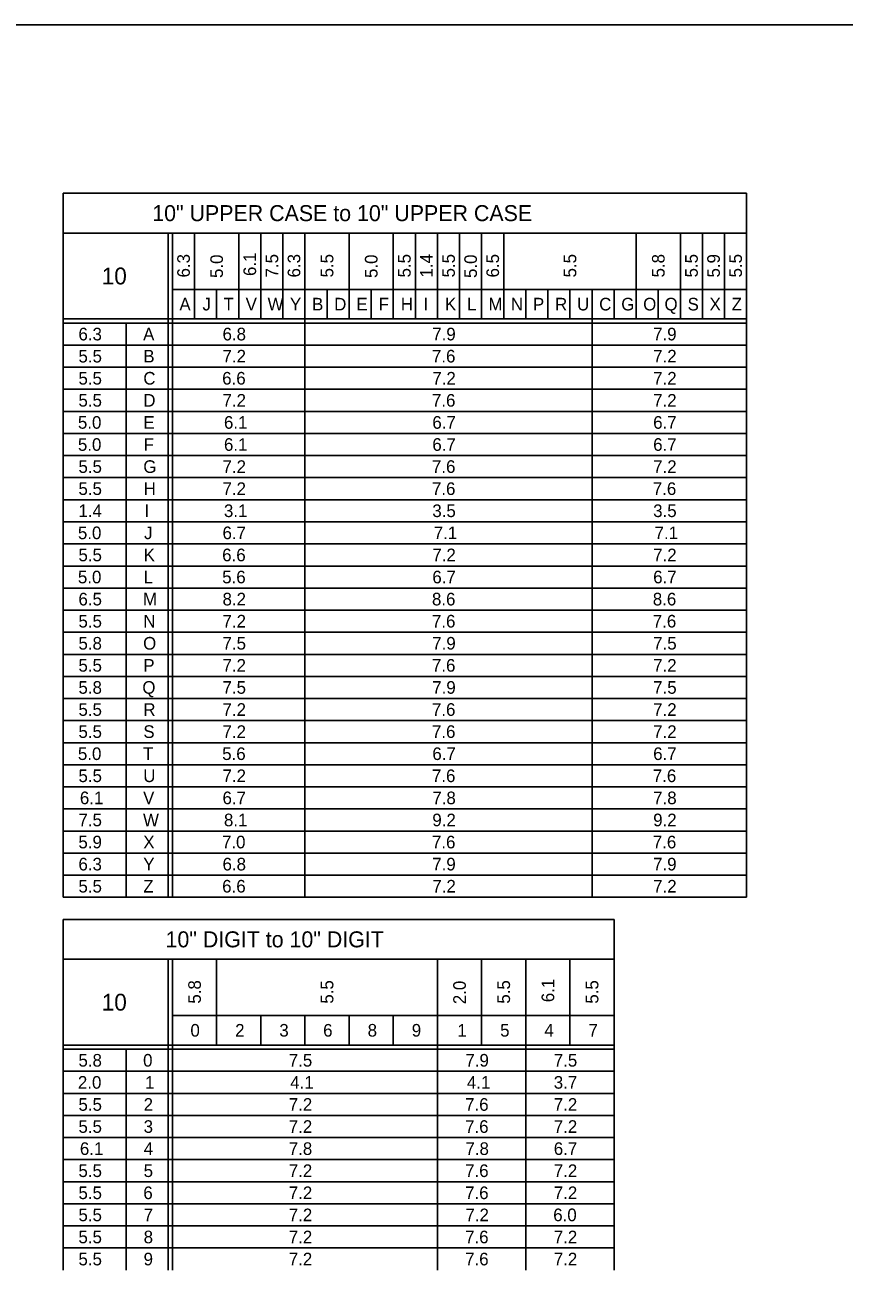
# Model space of a CAD drawing. Extents: x 637580 to 641849, y 297270 to 299646.
# Drawn here: x 640540.8 to 640735.6, y 297552.6 to 297848.6 of the extents above; entities that cross this region are included whole.
import ezdxf

# ---------------------------------------------------------------- set-up
doc = ezdxf.new("R2010")
doc.units = 0
doc.layers.add('1', color=7, linetype='Continuous')
doc.layers.add('2', color=7, linetype='Continuous')

msp = doc.modelspace()

# ---------------------------------------------------------------- linework, layer by layer
at = {"layer": '1'}
msp.add_line((640143.31, 297848.63), (640929.31, 297848.63), dxfattribs=at)
at = {"layer": '2'}
for p, q in [((640712.41, 297808.63), (640549.91, 297808.63)), ((640549.91, 297808.63), (640549.91, 297641.25)), ((640712.41, 297808.63), (640712.41, 297641.25)), ((640549.91, 297799.13), (640712.41, 297799.13)), ((640574.91, 297799.13), (640574.91, 297641.25)), ((640575.91, 297799.13), (640575.91, 297641.25)), ((640581.16, 297799.13), (640581.16, 297778.75)), ((640591.66, 297799.13), (640591.66, 297778.75)), ((640596.91, 297799.13), (640596.91, 297778.75)), ((640602.16, 297799.13), (640602.16, 297778.75)), ((640607.41, 297799.13), (640607.41, 297641.25)), ((640617.91, 297799.13), (640617.91, 297778.75)), ((640628.41, 297799.13), (640628.41, 297778.75)), ((640633.66, 297799.13), (640633.66, 297778.75)), ((640638.91, 297799.13), (640638.91, 297778.75)), ((640644.16, 297799.13), (640644.16, 297778.75)), ((640649.41, 297799.13), (640649.41, 297778.75)), ((640654.66, 297799.13), (640654.66, 297778.75)), ((640686.16, 297799.13), (640686.16, 297778.75)), ((640696.66, 297799.13), (640696.66, 297778.75)), ((640701.91, 297799.13), (640701.91, 297778.75)), ((640707.16, 297799.13), (640707.16, 297778.75)), ((640575.91, 297785.75), (640712.41, 297785.75)), ((640586.41, 297785.75), (640586.41, 297778.75)), ((640612.66, 297785.75), (640612.66, 297778.75)), ((640623.16, 297785.75), (640623.16, 297778.75)), ((640659.91, 297785.75), (640659.91, 297778.75)), ((640665.16, 297785.75), (640665.16, 297778.75)), ((640670.41, 297785.75), (640670.41, 297778.75)), ((640670.41, 297785.75), (640670.41, 297778.75)), ((640675.66, 297785.75), (640675.66, 297641.25)), ((640680.91, 297785.75), (640680.91, 297778.75)), ((640691.41, 297785.75), (640691.41, 297778.75)), ((640712.41, 297778.75), (640549.91, 297778.75)), ((640712.41, 297777.75), (640549.91, 297777.75)), ((640564.91, 297777.75), (640564.91, 297641.25)), ((640712.41, 297772.5), (640549.91, 297772.5)), ((640712.41, 297767.25), (640549.91, 297767.25)), ((640712.41, 297762), (640549.91, 297762)), ((640712.41, 297756.75), (640549.91, 297756.75)), ((640712.41, 297751.5), (640549.91, 297751.5)), ((640712.41, 297746.25), (640549.91, 297746.25)), ((640712.41, 297741), (640549.91, 297741)), ((640712.41, 297735.75), (640549.91, 297735.75)), ((640712.41, 297730.5), (640549.91, 297730.5)), ((640712.41, 297725.25), (640549.91, 297725.25)), ((640712.41, 297720), (640549.91, 297720)), ((640712.41, 297714.75), (640549.91, 297714.75)), ((640712.41, 297709.5), (640549.91, 297709.5)), ((640712.41, 297704.25), (640549.91, 297704.25)), ((640712.41, 297699), (640549.91, 297699)), ((640712.41, 297693.75), (640549.91, 297693.75)), ((640712.41, 297688.5), (640549.91, 297688.5)), ((640712.41, 297683.25), (640549.91, 297683.25)), ((640712.41, 297678), (640549.91, 297678)), ((640712.41, 297672.75), (640549.91, 297672.75)), ((640712.41, 297667.5), (640549.91, 297667.5)), ((640712.41, 297662.25), (640549.91, 297662.25)), ((640712.41, 297657), (640549.91, 297657)), ((640712.41, 297651.75), (640549.91, 297651.75)), ((640712.41, 297646.5), (640549.91, 297646.5)), ((640549.91, 297641.25), (640549.91, 297641.25)), ((640549.91, 297641.25), (640712.41, 297641.25)), ((640680.91, 297636), (640549.91, 297636)), ((640549.91, 297636), (640549.91, 297552.63)), ((640680.91, 297552.63), (640680.91, 297636)), ((640549.91, 297626.5), (640680.91, 297626.5)), ((640574.91, 297626.5), (640574.91, 297552.63)), ((640575.91, 297626.5), (640575.91, 297552.63)), ((640586.41, 297626.5), (640586.41, 297606.13)), ((640638.91, 297626.5), (640638.91, 297552.63)), ((640649.41, 297626.5), (640649.41, 297606.13)), ((640659.91, 297626.5), (640659.91, 297552.63)), ((640670.41, 297626.5), (640670.41, 297606.13)), ((640575.91, 297613.13), (640680.91, 297613.13)), ((640596.91, 297613.13), (640596.91, 297606.13)), ((640607.41, 297613.13), (640607.41, 297606.13)), ((640617.91, 297613.13), (640617.91, 297606.13)), ((640628.41, 297613.13), (640628.41, 297606.13)), ((640680.91, 297606.13), (640549.91, 297606.13)), ((640680.91, 297605.13), (640549.91, 297605.13)), ((640564.91, 297605.13), (640564.91, 297552.63)), ((640680.91, 297599.88), (640549.91, 297599.88)), ((640680.91, 297594.63), (640549.91, 297594.63)), ((640680.91, 297589.38), (640549.91, 297589.38)), ((640680.91, 297584.13), (640549.91, 297584.13)), ((640680.91, 297578.88), (640549.91, 297578.88)), ((640680.91, 297573.63), (640549.91, 297573.63)), ((640680.91, 297568.38), (640549.91, 297568.38)), ((640680.91, 297563.13), (640549.91, 297563.13)), ((640680.91, 297557.88), (640549.91, 297557.88))]:
    msp.add_line(p, q, dxfattribs=at)

# ---------------------------------------------------------------- texts
for s, height, p in [('10" UPPER CASE to 10" UPPER CASE', 3.8, (640571.1, 297801.98)), ('10', 4, (640559.1, 297786.94)), ('A', 3, (640577.56, 297780.75)), ('J', 3, (640583.04, 297780.75)), ('T', 3, (640588.04, 297780.75)), ('V', 3, (640593.31, 297780.75)), ('W', 3, (640598.53, 297780.75)), ('Y', 3, (640603.84, 297780.75)), ('B', 3, (640609.1, 297780.75)), ('D', 3, (640614.35, 297780.75)), ('E', 3, (640619.62, 297780.75)), ('F', 3, (640624.92, 297780.75)), ('H', 3, (640630.19, 297780.75)), ('I', 3, (640635.6, 297780.75)), ('K', 3, (640640.69, 297780.75)), ('L', 3, (640645.94, 297780.75)), ('M', 3, (640651.03, 297780.75)), ('N', 3, (640656.35, 297780.75)), ('P', 3, (640661.6, 297780.75)), ('R', 3, (640666.85, 297780.75)), ('U', 3, (640672.09, 297780.75)), ('C', 3, (640677.35, 297780.75)), ('G', 3, (640682.6, 297780.75)), ('O', 3, (640687.81, 297780.75)), ('Q', 3, (640692.88, 297780.75)), ('S', 3, (640698.37, 297780.75)), ('X', 3, (640703.59, 297780.75)), ('Z', 3, (640708.85, 297780.75)), ('6.3', 3, (640553.56, 297773.63)), ('A', 3, (640568.93, 297773.63)), ('6.8', 3, (640587.81, 297773.63)), ('7.9', 3, (640637.67, 297773.63)), ('7.9', 3, (640690.17, 297773.63)), ('5.5', 3, (640553.56, 297768.38)), ('B', 3, (640568.98, 297768.38)), ('7.2', 3, (640587.81, 297768.38)), ('7.6', 3, (640637.6, 297768.38)), ('7.2', 3, (640690.19, 297768.38)), ('5.5', 3, (640553.56, 297763.13)), ('C', 3, (640568.98, 297763.13)), ('6.6', 3, (640587.73, 297763.13)), ('7.2', 3, (640637.69, 297763.13)), ('7.2', 3, (640690.19, 297763.13)), ('5.5', 3, (640553.56, 297757.88)), ('D', 3, (640568.98, 297757.88)), ('7.2', 3, (640587.81, 297757.88)), ('7.6', 3, (640637.6, 297757.88)), ('7.2', 3, (640690.19, 297757.88)), ('5.0', 3, (640553.43, 297752.63)), ('E', 3, (640568.99, 297752.63)), ('6.1', 3, (640588.15, 297752.63)), ('6.7', 3, (640637.69, 297752.63)), ('6.7', 3, (640690.19, 297752.63)), ('5.0', 3, (640553.43, 297747.38)), ('F', 3, (640569.05, 297747.38)), ('6.1', 3, (640588.15, 297747.38)), ('6.7', 3, (640637.69, 297747.38)), ('6.7', 3, (640690.19, 297747.38)), ('5.5', 3, (640553.56, 297742.13)), ('G', 3, (640568.98, 297742.13)), ('7.2', 3, (640587.81, 297742.13)), ('7.6', 3, (640637.6, 297742.13)), ('7.2', 3, (640690.19, 297742.13)), ('5.5', 3, (640553.56, 297736.88)), ('H', 3, (640569.06, 297736.88)), ('7.2', 3, (640587.81, 297736.88)), ('7.6', 3, (640637.6, 297736.88)), ('7.6', 3, (640690.1, 297736.88)), ('1.4', 3, (640553.56, 297731.63)), ('I', 3, (640569.23, 297731.63)), ('3.1', 3, (640588.15, 297731.63)), ('3.5', 3, (640637.69, 297731.63)), ('3.5', 3, (640690.19, 297731.63)), ('5.0', 3, (640553.43, 297726.38)), ('J', 3, (640569.17, 297726.38)), ('6.7', 3, (640587.81, 297726.38)), ('7.1', 3, (640638.03, 297726.38)), ('7.1', 3, (640690.53, 297726.38)), ('5.5', 3, (640553.56, 297721.13)), ('K', 3, (640569.06, 297721.13)), ('6.6', 3, (640587.73, 297721.13)), ('7.2', 3, (640637.69, 297721.13)), ('7.2', 3, (640690.19, 297721.13)), ('5.0', 3, (640553.43, 297715.88)), ('L', 3, (640569.06, 297715.88)), ('5.6', 3, (640587.73, 297715.88)), ('6.7', 3, (640637.69, 297715.88)), ('6.7', 3, (640690.19, 297715.88)), ('6.5', 3, (640553.56, 297710.63)), ('M', 3, (640568.91, 297710.63)), ('8.2', 3, (640587.81, 297710.63)), ('8.6', 3, (640637.6, 297710.63)), ('8.6', 3, (640690.1, 297710.63)), ('5.5', 3, (640553.56, 297705.38)), ('N', 3, (640568.98, 297705.38)), ('7.2', 3, (640587.81, 297705.38)), ('7.6', 3, (640637.6, 297705.38)), ('7.6', 3, (640690.1, 297705.38)), ('5.8', 3, (640553.56, 297700.13)), ('O', 3, (640568.93, 297700.13)), ('7.5', 3, (640587.81, 297700.13)), ('7.9', 3, (640637.67, 297700.13)), ('7.5', 3, (640690.19, 297700.13)), ('5.5', 3, (640553.56, 297694.88)), ('P', 3, (640568.98, 297694.88)), ('7.2', 3, (640587.81, 297694.88)), ('7.6', 3, (640637.6, 297694.88)), ('7.2', 3, (640690.19, 297694.88)), ('5.8', 3, (640553.56, 297689.63)), ('Q', 3, (640568.75, 297689.63)), ('7.5', 3, (640587.81, 297689.63)), ('7.9', 3, (640637.67, 297689.63)), ('7.5', 3, (640690.19, 297689.63)), ('5.5', 3, (640553.56, 297684.38)), ('R', 3, (640568.98, 297684.38)), ('7.2', 3, (640587.81, 297684.38)), ('7.6', 3, (640637.6, 297684.38)), ('7.2', 3, (640690.19, 297684.38)), ('5.5', 3, (640553.56, 297679.13)), ('S', 3, (640568.99, 297679.13)), ('7.2', 3, (640587.81, 297679.13)), ('7.6', 3, (640637.6, 297679.13)), ('7.2', 3, (640690.19, 297679.13)), ('5.0', 3, (640553.43, 297673.88)), ('T', 3, (640568.92, 297673.88)), ('5.6', 3, (640587.73, 297673.88)), ('6.7', 3, (640637.69, 297673.88)), ('6.7', 3, (640690.19, 297673.88)), ('5.5', 3, (640553.56, 297668.63)), ('U', 3, (640568.97, 297668.63)), ('7.2', 3, (640587.81, 297668.63)), ('7.6', 3, (640637.6, 297668.63)), ('7.6', 3, (640690.1, 297668.63)), ('6.1', 3, (640553.9, 297663.38)), ('V', 3, (640568.93, 297663.38)), ('6.7', 3, (640587.81, 297663.38)), ('7.8', 3, (640637.69, 297663.38)), ('7.8', 3, (640690.19, 297663.38)), ('7.5', 3, (640553.56, 297658.13)), ('W', 3, (640568.91, 297658.13)), ('8.1', 3, (640588.15, 297658.13)), ('9.2', 3, (640637.69, 297658.13)), ('9.2', 3, (640690.19, 297658.13)), ('5.9', 3, (640553.55, 297652.88)), ('X', 3, (640568.97, 297652.88)), ('7.0', 3, (640587.68, 297652.88)), ('7.6', 3, (640637.6, 297652.88)), ('7.6', 3, (640690.1, 297652.88)), ('6.3', 3, (640553.56, 297647.63)), ('Y', 3, (640568.97, 297647.63)), ('6.8', 3, (640587.81, 297647.63)), ('7.9', 3, (640637.67, 297647.63)), ('7.9', 3, (640690.17, 297647.63)), ('5.5', 3, (640553.56, 297642.38)), ('Z', 3, (640568.98, 297642.38)), ('6.6', 3, (640587.73, 297642.38)), ('7.2', 3, (640637.69, 297642.38)), ('7.2', 3, (640690.19, 297642.38)), ('10" DIGIT to 10" DIGIT', 3.8, (640574.26, 297629.35)), ('10', 4, (640559.1, 297614.31)), ('0', 3, (640580.18, 297608.13)), ('2', 3, (640590.81, 297608.13)), ('3', 3, (640601.31, 297608.13)), ('6', 3, (640611.73, 297608.13)), ('8', 3, (640622.31, 297608.13)), ('9', 3, (640632.8, 297608.13)), ('1', 3, (640643.65, 297608.13)), ('5', 3, (640653.81, 297608.13)), ('4', 3, (640664.31, 297608.13)), ('7', 3, (640674.81, 297608.13)), ('5.8', 3, (640553.56, 297601)), ('0', 3, (640568.93, 297601)), ('7.5', 3, (640603.56, 297601)), ('7.9', 3, (640645.55, 297601)), ('7.5', 3, (640666.56, 297601)), ('2.0', 3, (640553.43, 297595.75)), ('1', 3, (640569.4, 297595.75)), ('4.1', 3, (640603.9, 297595.75)), ('4.1', 3, (640645.9, 297595.75)), ('3.7', 3, (640666.56, 297595.75)), ('5.5', 3, (640553.56, 297590.5)), ('2', 3, (640569.06, 297590.5)), ('7.2', 3, (640603.56, 297590.5)), ('7.6', 3, (640645.48, 297590.5)), ('7.2', 3, (640666.56, 297590.5)), ('5.5', 3, (640553.56, 297585.25)), ('3', 3, (640569.06, 297585.25)), ('7.2', 3, (640603.56, 297585.25)), ('7.6', 3, (640645.48, 297585.25)), ('7.2', 3, (640666.56, 297585.25)), ('6.1', 3, (640553.9, 297580)), ('4', 3, (640569.06, 297580)), ('7.8', 3, (640603.56, 297580)), ('7.8', 3, (640645.56, 297580)), ('6.7', 3, (640666.56, 297580)), ('5.5', 3, (640553.56, 297574.75)), ('5', 3, (640569.06, 297574.75)), ('7.2', 3, (640603.56, 297574.75)), ('7.6', 3, (640645.48, 297574.75)), ('7.2', 3, (640666.56, 297574.75)), ('5.5', 3, (640553.56, 297569.5)), ('6', 3, (640568.98, 297569.5)), ('7.2', 3, (640603.56, 297569.5)), ('7.6', 3, (640645.48, 297569.5)), ('7.2', 3, (640666.56, 297569.5)), ('5.5', 3, (640553.56, 297564.25)), ('7', 3, (640569.06, 297564.25)), ('7.2', 3, (640603.56, 297564.25)), ('7.2', 3, (640645.56, 297564.25)), ('6.0', 3, (640666.43, 297564.25)), ('5.5', 3, (640553.56, 297559)), ('8', 3, (640569.06, 297559)), ('7.2', 3, (640603.56, 297559)), ('7.6', 3, (640645.48, 297559)), ('7.2', 3, (640666.56, 297559)), ('5.5', 3, (640553.56, 297553.75)), ('9', 3, (640569.05, 297553.75)), ('7.2', 3, (640603.56, 297553.75)), ('7.6', 3, (640645.48, 297553.75)), ('7.2', 3, (640666.56, 297553.75))]:
    msp.add_text(s, height=height, dxfattribs=at).set_placement(p)
for s, p in [('6.3', (640580.04, 297788.59)), ('5.0', (640587.91, 297788.46)), ('6.1', (640595.79, 297788.93)), ('7.5', (640601.04, 297788.59)), ('6.3', (640606.29, 297788.59)), ('5.5', (640614.16, 297788.59)), ('5.0', (640624.66, 297788.46)), ('5.5', (640632.54, 297788.59)), ('1.4', (640637.79, 297788.59)), ('5.5', (640643.04, 297788.59)), ('5.0', (640648.29, 297788.46)), ('6.5', (640653.54, 297788.59)), ('5.5', (640671.91, 297788.59)), ('5.8', (640692.91, 297788.59)), ('5.5', (640700.79, 297788.59)), ('5.9', (640706.04, 297788.58)), ('5.5', (640711.29, 297788.59)), ('5.8', (640582.66, 297615.96)), ('5.5', (640614.16, 297615.96)), ('2.0', (640645.66, 297615.83)), ('5.5', (640656.16, 297615.96)), ('6.1', (640666.66, 297616.31)), ('5.5', (640677.16, 297615.96))]:
    msp.add_text(s, height=3, rotation=90, dxfattribs=at).set_placement(p)

doc.saveas('drawing.dxf')
